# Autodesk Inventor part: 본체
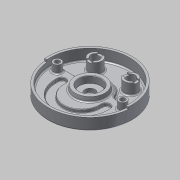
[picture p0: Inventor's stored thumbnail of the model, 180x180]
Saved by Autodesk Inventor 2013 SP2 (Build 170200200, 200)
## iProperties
Created: 2015-04
Part Number: 본체
Material: 알루미늄 6061
Document SubType Name: Modeling
Designer: dgall
Density: 2.71 g/cm^3
Mass: 1044.55 g
Surface Area: 1020.02 cm^2
Volume: 385.443 cm^3
Author: dgall
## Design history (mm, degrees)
sketch "스케치1"
  geometry: C1 r 95 at (0, 0); 1 further point
  constraints: 1 centre point, 1 coincident
  dimensions: "d0" = 190 diameter of C1
extrude "돌출1" new body sketch "스케치1" distance "d2" = 32; taper "d3" = 0 deg
sketch "스케치2"
  geometry: L1 (-76.916, 12)-(-47.117, 12); L2 (-40.249, 12)-(40.249, 12); L3 (47.117, 12)-(76.916, 12); L4 (-73.457, 52)-(73.457, 52); L5 (0, 42)-(0, 0); L6 (-46, 65.748)-(-46, 38.252); L7 (-34, 65.748)-(-34, 38.252); L8 (26.252, 58)-(53.748, 58); L9 (53.748, 46)-(26.252, 46); C1 r 95 at (0, 0) reference; C2 r 10 at (-40, 52); C3 r 10 at (40, 52); A1 r 90 centre (0, 0) between (86.53, 24.75) and (-86.53, 24.75); A2 r 10 centre (-76.916, 22) between (-86.53, 24.75) and (-76.916, 12); A3 r 10 centre (-47.117, 22) between (-47.117, 12) and (-38.056, 17.769); A4 r 10 centre (47.117, 22) between (38.056, 17.769) and (47.117, 12); A5 r 10 centre (76.916, 22) between (76.916, 12) and (86.53, 24.75); A6 r 42 centre (0, 0) between (-40.249, 12) and (40.249, 12); A7 r 42 centre (0, 0) between (38.056, 17.769) and (-38.056, 17.769); A8 r 15 centre (-40, 52) between (-46, 65.748) and (-46, 38.252); A9 r 15 centre (40, 52) between (26.252, 58) and (53.748, 58)
  constraints: 25 point on circle, 18 end point, 14 tangent, 11 centre point, 6 parallel, 4 coincident, 3 horizontal, 2 perpendicular, 2 symmetric about line, 1 point on line, 2 other
  dimensions: "d6" = 180 diameter of A1; "d8" = 20 diameter of A2; "d9" = 20 diameter of A3; "d10" = 20 diameter of A4; "d11" = 20 diameter of A5; "d12" = 22 vertical distance of C1.centre A3.centre; "d13" = 42 radius of A7; "d15" = 29.79866 distance of A3.centre A2.centre; "d16" = 29.79866 distance of A5.centre A4.centre; "d17" = 52 distance from line of C1.centre L4; "d18" = 40 horizontal distance of C1.centre A8.centre; "d19" = 30 diameter of A8; "d20" = 20 diameter of C2; "d21" = 12 distance between parallel lines of L7 L6; "d23" = 12 distance between parallel lines of L9 L8
extrude "돌출2" cut sketch "스케치2" distance "d24" = 25; taper "d25" = 0 deg
extrude "돌출3" cut sketch "스케치2" stored distance "d26" = 25; taper "d27" = 0 deg
extrude "돌출4" cut sketch "스케치2" distance "d28" = 3; taper "d29" = 0 deg
sketch "스케치3"
  geometry: L1 (-47.117, 12)-(-76.916, 12) reference; L2 (76.916, 12)-(47.117, 12) reference; C1 r 95 at (0, 0) reference; C2 r 90 at (0, 0); A1 r 10 centre (-47.117, 22) between (-47.117, 12) and (-38.056, 17.769) reference; A2 r 10 centre (-76.916, 22) between (-86.53, 24.75) and (-76.916, 12) reference; A3 r 90 centre (0, 0) between (86.53, 24.75) and (-86.53, 24.75) reference; A4 r 10 centre (76.916, 22) between (76.916, 12) and (86.53, 24.75) reference; A5 r 10 centre (47.117, 22) between (38.056, 17.769) and (47.117, 12) reference; A6 r 42 centre (0, 0) between (38.056, 17.769) and (-38.056, 17.769) reference
  constraints: 1 centre point, 1 coincident
  dimensions: "d30" = 180 diameter of C2
extrude "돌출5" cut sketch "스케치3" distance "d34" = 18; taper "d35" = 0 deg
sketch "스케치4"
  geometry: C1 r 35 at (0, 0); C2 r 25 at (0, 0); A1 r 42 centre (0, 0) between (38.056, 17.769) and (-38.056, 17.769) reference
  constraints: 2 centre point, 2 coincident
  dimensions: "d36" = 70 diameter of C1; "d38" = 50 diameter of C2
extrude "돌출6" join sketch "스케치4" distance "d39" = 10; taper "d40" = 0 deg
sketch "스케치5"
  geometry: C1 r 25 at (0, 0) reference; C2 r 11.5 at (0, 0)
  constraints: 1 centre point, 1 coincident
  dimensions: "d41" = 23 diameter of C2
extrude "돌출7" cut sketch "스케치5" stored distance "d43" = 10; taper "d44" = 0 deg
sketch "스케치6"
  geometry: L1 (-76.916, 12)-(-47.117, 12) reference; L2 (-87.972, -19)-(87.972, -19); L3 (-59, -19)-(59, -19); L4 (-59, -19)-(-59, -14); L5 (-41, -19)-(-41, -14); L6 (-59, -14)-(-41, -14); L7 (0, -19)-(0, -60); L8 (59, -19)-(59, -14); L9 (41, -19)-(41, -14); C1 r 35 at (0, 0) reference; C2 r 42 at (0, 0); A1 r 90 centre (0, 0) between (-86.53, 24.75) and (86.53, 24.75) reference; A2 r 41 centre (0, -19) between (-41, -19) and (41, -19); A3 r 59 centre (0, -19) between (-59, -19) and (59, -19); A4 r 9 centre (-50, -14) between (-41, -14) and (-59, -14); A5 r 9 centre (50, -14) between (59, -14) and (41, -14)
  constraints: 16 end point, 11 point on circle, 5 centre point, 4 point on line, 3 symmetric about line, 2 coincident, 2 midpoint, 2 parallel, 2 perpendicular, 2 tangent, 1 other
  dimensions: "d45" = 19 distance from line of L2 A1.centre; "d50" = 84 diameter of C2; "d52" = 59 radius of A3; "d53" = 41 radius of A2; "d54" = 5 vertical distance of L7.start A4.centre
extrude "돌출8" cut sketch "스케치6" distance "d55" = 7; taper "d56" = 0 deg
sketch "스케치7"
  geometry: C1 r 9 at (-74, 0); C2 r 5.5 at (-74, 0); A1 r 90 centre (0, 0) between (-86.53, 24.75) and (86.53, 24.75) reference
  constraints: 2 centre point, 1 coincident, 1 horizontal alignment
  dimensions: "d57" = 18 diameter of C1; "d59" = 11 diameter of C2; "d60" = 74 distance of A1.centre C2.centre
extrude "돌출9" join sketch "스케치7" distance "d61" = 18; taper "d62" = 0 deg
extrude "돌출10" cut sketch "스케치7" stored distance "d63" = 13; taper "d64" = 0 deg
sketch "스케치9"
  geometry: C1 r 5.5 at (-74, 0) reference; C2 r 5.5 at (74, 0) reference; C3 r 9 at (-74, 0); C4 r 9 at (74, 0)
  constraints: 2 centre point, 2 coincident, 1 equal radius
  dimensions: "d65" = 18 diameter of C3
extrude "돌출11" cut sketch "스케치9" distance "d67" = 11; taper "d68" = 0 deg
sketch "스케치10"
  geometry: L1 (0, 0)-(-94.638, -8.28); L2 (0, 0)-(94.638, -8.28); L3 (-95, 0)-(95, 0); L4 (-94.638, -8.28)-(-89.658, -7.844); L5 (89.658, -7.844)-(94.638, -8.28); A1 r 95 centre (0, 0) between (-94.638, -8.28) and (94.638, -8.28) reference; A2 r 95 centre (0, 0) between (-94.638, -8.28) and (94.638, -8.28); A3 r 90 centre (0, 0) between (-89.658, -7.844) and (89.658, -7.844)
  constraints: 10 end point, 8 point on circle, 2 centre point, 2 coincident, 2 collinear, 1 horizontal, 1 point on line, 2 other
  dimensions: "d69" = 5 deg angle of L2 L3; "d70" = 5 deg angle of L1 L3
extrude "돌출12" cut sketch "스케치10" distance "d71" = 5; taper "d72" = 0 deg
sketch "스케치11"
  geometry: L1 (-19, 14)-(-60, 14) reference; L2 (-35, 14)-(-35, 24) reference; L3 (-35, 14)-(-33.237, 24); L4 (-35, 30.674)-(-35.032, 30.674); L5 (-35.027, 24)-(-35, 14); L6 (35, 24)-(-35, 24) reference; L7 (-35.027, 24)-(-33.237, 24); L8 (0, 0)-(0, 44.642)
  constraints: 10 end point, 3 point on line, 1 collinear, 1 horizontal, 1 perpendicular
  dimensions: "d73" = 100 deg angle of L1 L3
revolve "회전1" sketch "스케치11" stored, may be unused: angle "d74" = 90 deg
sketch "스케치12"
  geometry: C1 r 25 at (0, 0) reference
extrude "돌출13" cut sketch "스케치12" distance "d75" = 15; taper "d76" = 0 deg
sketch "스케치13"
  geometry: L1 (-36.062, -36.062)-(-50.912, -50.912); L2 (36.062, -36.062)-(50.912, -50.912); L3 (0, 0)-(0, -72); C1 r 95 at (0, 0) reference; A1 r 72 centre (0, 0) between (-50.912, -50.912) and (50.912, -50.912); A2 r 51 centre (0, 0) between (-36.062, -36.062) and (36.062, -36.062); 1 further point
  constraints: 6 end point, 5 point on circle, 2 centre point, 2 coincident, 1 vertical
  dimensions: "d83" = 144 diameter of A1; "d85" = 102 diameter of A2; "d86" = 90 deg angle of L2 L1; "d87" = 45 deg angle of L1 L3
extrude "돌출14" join sketch "스케치13" distance "d88" = 5; taper "d89" = 0 deg
sketch "스케치14"
  geometry: L1 (-36.062, -36.062)-(-50.912, -50.912) reference; L2 (50.912, -50.912)-(36.062, -36.062) reference; A1 r 72 centre (0, 0) between (-50.912, -50.912) and (50.912, -50.912) reference; A2 r 51 centre (0, 0) between (-36.062, -36.062) and (36.062, -36.062) reference
fillet "모깎기1" dims "d92" = 5
fillet "모깎기2" dims "d93" = 5
fillet "모깎기3" dims "d94" = 3
chamfer "모따기1" distance "d95" = 1; stored, may be unused: second distance "d96" = 2, angle "d97" = 45 deg
fillet "모깎기4" dims "d98" = 1
fillet "모깎기5" dims "d99" = 3
fillet "모깎기7" dims "d101" = 0.3
node "솔리드1"
mirror "대칭1"
other parameters: "d4" = 84, "d7" = 12, "d46" = 118, "d47" = 82, "d51" = 5
